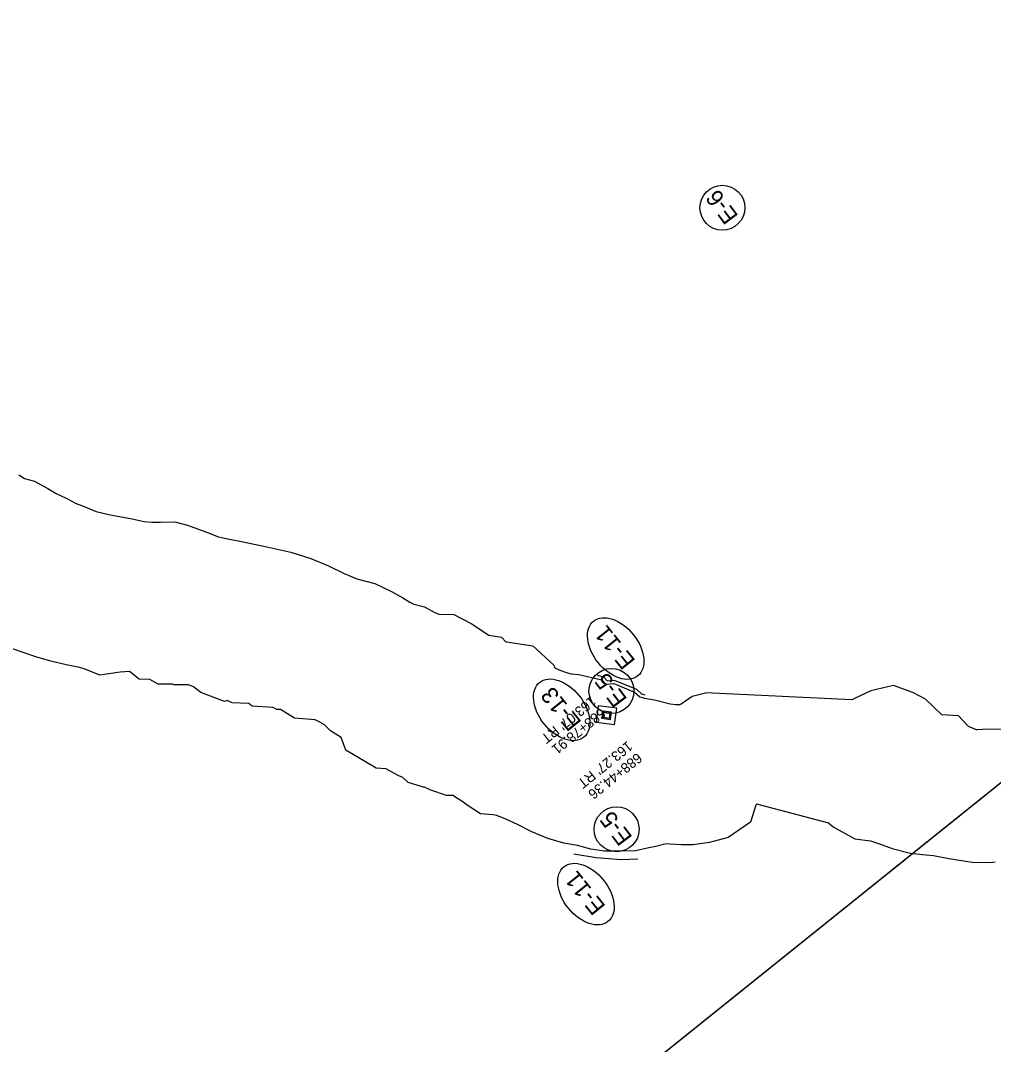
# Model space of a CAD drawing. Extents: x 641687 to 655797, y 406445 to 431088.
# Drawn here: x 651614 to 652196, y 415670 to 416282 of the extents above; entities that cross this region are included whole.
import ezdxf

# ---------------------------------------------------------------- set-up
doc = ezdxf.new("R2010")
doc.units = 0
for name, color, linetype in [('2', 7, 'Continuous'), ('R_Erosion', 7, 'Continuous'), ('R_Erosion_Buffer', 7, 'Continuous'), ('R_Erosion_Silt Fence', 7, 'Continuous'), ('R_No Plot', 7, 'Continuous')]:
    doc.layers.add(name, color=color, linetype=linetype)

msp = doc.modelspace()

# ---------------------------------------------------------------- linework, layer by layer
at = {"layer": '2'}
msp.add_lwpolyline([(651966.84, 415867.96), (651962.87, 415868.46), (651962.49, 415865.48), (651966.46, 415864.98)], close=True, dxfattribs=at)
at = {"layer": 'R_Erosion'}
for points in [[(651958.33, 415862.58), (651969.43, 415861.18), (651970.66, 415870.93), (651959.56, 415872.33)], [(651961.75, 415864.91), (651967.04, 415864.24), (651967.58, 415868.54), (651962.29, 415869.21)]]:
    msp.add_lwpolyline(points, close=True, dxfattribs=at)
for centre in [(652033.84, 416170.11), (651967.54, 415881.2), (651970.62, 415798.56)]:
    msp.add_circle(centre, 13.44, dxfattribs=at)
for centre in [(651970.07, 415906.6), (651937.8, 415869.96), (651952.29, 415759.77)]:
    msp.add_ellipse(centre, major_axis=(-13.17, 16.41), ratio=0.638788, dxfattribs=at)
at = {"layer": 'R_Erosion_Buffer'}
for points in [[(651613.34, 416010.39), (651616.81, 416008.23), (651622.73, 416006.75), (651630.66, 416002.24), (651635.68, 415999.22), (651641.68, 415996.41), (651647.68, 415993.25), (651652.55, 415991.52), (651659.6, 415988.57), (651667.91, 415986.59), (651680.14, 415984.28), (651688.33, 415982.5), (651692.94, 415982.19), (651698.1, 415982.19), (651706.63, 415982.38), (651714.19, 415980.41), (651726.07, 415975.87), (651732.76, 415973.4), (651737.24, 415972.47), (651747.46, 415970.39), (651761.51, 415967.35), (651776.01, 415964.13), (651787.93, 415960.46), (651798.52, 415955.94), (651807.85, 415951.37), (651815.38, 415948.32), (651826.1, 415945.41), (651836.04, 415940.69), (651842.87, 415936.96), (651847.05, 415934.28), (651849.53, 415933.11), (651855.8, 415931.48), (651861.67, 415928.37), (651864.4, 415927.2), (651864.66, 415927.16), (651873.37, 415926.9), (651883.63, 415921.47), (651894.28, 415914.64), (651901.84, 415913.43), (651904.5, 415910.58), (651904.84, 415910.64), (651920.51, 415908.19), (651933.13, 415896.62), (651933.78, 415895.05), (651936.66, 415893.71), (651941.22, 415892.16), (651943.51, 415891.38), (651948.08, 415891.09), (651961.8, 415887.86), (651964.2, 415885.25), (651968.86, 415885.7), (651981.35, 415880.5), (651984.59, 415877.68), (651987.34, 415876.98), (651993.29, 415875.86), (652002.65, 415873.46), (652006.05, 415873.19), (652008.48, 415873.1), (652009.13, 415873.47), (652015.81, 415878.07), (652023.69, 415880.17)], [(651613.34, 416010.39), (651616.81, 416008.23), (651622.73, 416006.75), (651630.66, 416002.24), (651635.68, 415999.22), (651641.68, 415996.41), (651647.68, 415993.25), (651652.55, 415991.52), (651659.6, 415988.57), (651667.91, 415986.59), (651680.14, 415984.28), (651688.33, 415982.5), (651692.94, 415982.19), (651698.1, 415982.19), (651706.63, 415982.38), (651714.19, 415980.41), (651726.07, 415975.87), (651732.76, 415973.4), (651737.24, 415972.47), (651747.46, 415970.39), (651761.51, 415967.35), (651776.01, 415964.13), (651787.93, 415960.46), (651798.52, 415955.94), (651807.85, 415951.37), (651815.38, 415948.32), (651826.1, 415945.41), (651836.04, 415940.69), (651842.87, 415936.96), (651847.05, 415934.28), (651849.53, 415933.11), (651855.8, 415931.48), (651861.67, 415928.37), (651864.4, 415927.2), (651864.66, 415927.16), (651873.37, 415926.9), (651883.63, 415921.47), (651894.28, 415914.64), (651901.84, 415913.43), (651904.5, 415910.58), (651904.84, 415910.64), (651920.51, 415908.19), (651933.13, 415896.62), (651933.78, 415895.05), (651936.66, 415893.71), (651941.22, 415892.16), (651943.51, 415891.38), (651948.08, 415891.09), (651961.8, 415887.86), (651964.2, 415885.25), (651968.86, 415885.7), (651981.35, 415880.5), (651984.59, 415877.68), (651987.34, 415876.98), (651993.29, 415875.86), (652002.65, 415873.46), (652006.05, 415873.19), (652008.48, 415873.1), (652009.13, 415873.47), (652015.81, 415878.07), (652023.69, 415880.17)], [(651613.34, 416010.39), (651616.81, 416008.23), (651622.73, 416006.75), (651630.66, 416002.24), (651635.68, 415999.22), (651641.68, 415996.41), (651647.68, 415993.25), (651652.55, 415991.52), (651659.6, 415988.57), (651667.91, 415986.59), (651680.14, 415984.28), (651688.33, 415982.5), (651692.94, 415982.19), (651698.1, 415982.19), (651706.63, 415982.38), (651714.19, 415980.41), (651726.07, 415975.87), (651732.76, 415973.4), (651737.24, 415972.47), (651747.46, 415970.39), (651761.51, 415967.35), (651776.01, 415964.13), (651787.93, 415960.46), (651798.52, 415955.94), (651807.85, 415951.37), (651815.38, 415948.32), (651826.1, 415945.41), (651836.04, 415940.69), (651842.87, 415936.96), (651847.05, 415934.28), (651849.53, 415933.11), (651855.8, 415931.48), (651861.67, 415928.37), (651864.4, 415927.2), (651864.66, 415927.16), (651873.37, 415926.9), (651883.63, 415921.47), (651894.28, 415914.64), (651901.84, 415913.43), (651904.5, 415910.58), (651904.84, 415910.64), (651920.51, 415908.19), (651933.13, 415896.62), (651933.78, 415895.05), (651936.66, 415893.71), (651941.22, 415892.16), (651943.51, 415891.38), (651948.08, 415891.09), (651961.8, 415887.86), (651964.2, 415885.25), (651968.86, 415885.7), (651981.35, 415880.5), (651984.59, 415877.68), (651987.34, 415876.98), (651993.29, 415875.86), (652002.65, 415873.46), (652006.05, 415873.19), (652008.48, 415873.1), (652009.13, 415873.47), (652015.81, 415878.07), (652023.69, 415880.17)], [(652054.15, 415813.85), (652053.74, 415812.95), (652050.72, 415802.88), (652037.23, 415793.7), (652026.17, 415790.72), (652016.28, 415789.28), (652009.28, 415789.28), (652002.35, 415789.56), (652000.17, 415789.84), (651994.09, 415788.32), (651989.89, 415787.53), (651981.96, 415785.71), (651973.45, 415785.52), (651963.45, 415785.52), (651955.26, 415786.72), (651947.23, 415788.8), (651939.11, 415790.24), (651929.44, 415793.12), (651919.95, 415797.08), (651911.49, 415801.38), (651904.35, 415804.68), (651899.07, 415806.73), (651896.79, 415807.26), (651889.29, 415807.86), (651881.29, 415813.04), (651878.16, 415815.33), (651874.6, 415817.6), (651872.91, 415818.71), (651868.91, 415818.66), (651859.53, 415821.89), (651855.81, 415823.65), (651855.27, 415823.78), (651846.13, 415826.45), (651842.92, 415829.45), (651840.42, 415830.59), (651833.05, 415834.57), (651833, 415834.6), (651826.97, 415835.1), (651808.81, 415845.83), (651806.09, 415853.45), (651799.75, 415857.48), (651796.02, 415860.96), (651793.29, 415862.65), (651790.84, 415863.87), (651790.3, 415864.05), (651788.02, 415864.1), (651778.08, 415864.88), (651769.75, 415870.09), (651767.6, 415870.22), (651765.38, 415871.27), (651752.83, 415872.1), (651750.82, 415873.83), (651740.87, 415874.12), (651737.85, 415875.49), (651736.28, 415874.88), (651722.23, 415880.29), (651717.99, 415883.56), (651717.38, 415883.91), (651714.54, 415884.84), (651706.12, 415884.84), (651705.26, 415885.34), (651696.61, 415885.34), (651691.71, 415888.14), (651685.34, 415888.38), (651679.48, 415892.87), (651673.93, 415892.4), (651661.79, 415890.7), (651652.5, 415894.47), (651649.58, 415895.23), (651641.78, 415896.79), (651632.52, 415899.04), (651623.57, 415901.7), (651609.68, 415906.37)], [(652054.15, 415813.85), (652053.74, 415812.95), (652050.72, 415802.88), (652037.23, 415793.7), (652026.17, 415790.72), (652016.28, 415789.28), (652009.28, 415789.28), (652002.35, 415789.56), (652000.17, 415789.84), (651994.09, 415788.32), (651989.89, 415787.53), (651981.96, 415785.71), (651973.45, 415785.52), (651963.45, 415785.52), (651955.26, 415786.72), (651947.23, 415788.8), (651939.11, 415790.24), (651929.44, 415793.12), (651919.95, 415797.08), (651911.49, 415801.38), (651904.35, 415804.68), (651899.07, 415806.73), (651896.79, 415807.26), (651889.29, 415807.86), (651881.29, 415813.04), (651878.16, 415815.33), (651874.6, 415817.6), (651872.91, 415818.71), (651868.91, 415818.66), (651859.53, 415821.89), (651855.81, 415823.65), (651855.27, 415823.78), (651846.13, 415826.45), (651842.92, 415829.45), (651840.42, 415830.59), (651833.05, 415834.57), (651833, 415834.6), (651826.97, 415835.1), (651808.81, 415845.83), (651806.09, 415853.45), (651799.75, 415857.48), (651796.02, 415860.96), (651793.29, 415862.65), (651790.84, 415863.87), (651790.3, 415864.05), (651788.02, 415864.1), (651778.08, 415864.88), (651769.75, 415870.09), (651767.6, 415870.22), (651765.38, 415871.27), (651752.83, 415872.1), (651750.82, 415873.83), (651740.87, 415874.12), (651737.85, 415875.49), (651736.28, 415874.88), (651722.23, 415880.29), (651717.99, 415883.56), (651717.38, 415883.91), (651714.54, 415884.84), (651706.12, 415884.84), (651705.26, 415885.34), (651696.61, 415885.34), (651691.71, 415888.14), (651685.34, 415888.38), (651679.48, 415892.87), (651673.93, 415892.4), (651661.79, 415890.7), (651652.5, 415894.47), (651649.58, 415895.23), (651641.78, 415896.79), (651632.52, 415899.04), (651623.57, 415901.7), (651609.68, 415906.37)], [(652054.15, 415813.85), (652053.74, 415812.95), (652050.72, 415802.88), (652037.23, 415793.7), (652026.17, 415790.72), (652016.28, 415789.28), (652009.28, 415789.28), (652002.35, 415789.56), (652000.17, 415789.84), (651994.09, 415788.32), (651989.89, 415787.53), (651981.96, 415785.71), (651973.45, 415785.52), (651963.45, 415785.52), (651955.26, 415786.72), (651947.23, 415788.8), (651939.11, 415790.24), (651929.44, 415793.12), (651919.95, 415797.08), (651911.49, 415801.38), (651904.35, 415804.68), (651899.07, 415806.73), (651896.79, 415807.26), (651889.29, 415807.86), (651881.29, 415813.04), (651878.16, 415815.33), (651874.6, 415817.6), (651872.91, 415818.71), (651868.91, 415818.66), (651859.53, 415821.89), (651855.81, 415823.65), (651855.27, 415823.78), (651846.13, 415826.45), (651842.92, 415829.45), (651840.42, 415830.59), (651833.05, 415834.57), (651833, 415834.6), (651826.97, 415835.1), (651808.81, 415845.83), (651806.09, 415853.45), (651799.75, 415857.48), (651796.02, 415860.96), (651793.29, 415862.65), (651790.84, 415863.87), (651790.3, 415864.05), (651788.02, 415864.1), (651778.08, 415864.88), (651769.75, 415870.09), (651767.6, 415870.22), (651765.38, 415871.27), (651752.83, 415872.1), (651750.82, 415873.83), (651740.87, 415874.12), (651737.85, 415875.49), (651736.28, 415874.88), (651722.23, 415880.29), (651717.99, 415883.56), (651717.38, 415883.91), (651714.54, 415884.84), (651706.12, 415884.84), (651705.26, 415885.34), (651696.61, 415885.34), (651691.71, 415888.14), (651685.34, 415888.38), (651679.48, 415892.87), (651673.93, 415892.4), (651661.79, 415890.7), (651652.5, 415894.47), (651649.58, 415895.23), (651641.78, 415896.79), (651632.52, 415899.04), (651623.57, 415901.7), (651609.68, 415906.37)], [(652202.83, 415858.26), (652192.41, 415858.41), (652186.14, 415858.05), (652185.58, 415858.03), (652180.91, 415860.07), (652180.78, 415860.14), (652174.88, 415866.43), (652165.03, 415866.88), (652155.13, 415876.33), (652147.72, 415880.33), (652136.08, 415884.49), (652122.57, 415881.4), (652112.73, 415876.74), (652111.33, 415875.84), (652023.69, 415880.17)], [(652202.83, 415858.26), (652192.41, 415858.41), (652186.14, 415858.05), (652185.58, 415858.03), (652180.91, 415860.07), (652180.78, 415860.14), (652174.88, 415866.43), (652165.03, 415866.88), (652155.13, 415876.33), (652147.72, 415880.33), (652136.08, 415884.49), (652122.57, 415881.4), (652112.73, 415876.74), (652111.33, 415875.84), (652023.69, 415880.17)], [(652202.83, 415858.26), (652192.41, 415858.41), (652186.14, 415858.05), (652185.58, 415858.03), (652180.91, 415860.07), (652180.78, 415860.14), (652174.88, 415866.43), (652165.03, 415866.88), (652155.13, 415876.33), (652147.72, 415880.33), (652136.08, 415884.49), (652122.57, 415881.4), (652112.73, 415876.74), (652111.33, 415875.84), (652023.69, 415880.17)], [(652054.15, 415813.85), (652097.14, 415802.49), (652099.99, 415799.94), (652113.03, 415792.88), (652122.34, 415791.57), (652127.13, 415790.1), (652135.29, 415787.14), (652146.16, 415784.26), (652153.4, 415783.49), (652160.01, 415782.95), (652169.13, 415781.01), (652183.07, 415778.82), (652194.13, 415778.64), (652196.82, 415779.11)], [(652054.15, 415813.85), (652097.14, 415802.49), (652099.99, 415799.94), (652113.03, 415792.88), (652122.34, 415791.57), (652127.13, 415790.1), (652135.29, 415787.14), (652146.16, 415784.26), (652153.4, 415783.49), (652160.01, 415782.95), (652169.13, 415781.01), (652183.07, 415778.82), (652194.13, 415778.64), (652196.82, 415779.11)], [(652054.15, 415813.85), (652097.14, 415802.49), (652099.99, 415799.94), (652113.03, 415792.88), (652122.34, 415791.57), (652127.13, 415790.1), (652135.29, 415787.14), (652146.16, 415784.26), (652153.4, 415783.49), (652160.01, 415782.95), (652169.13, 415781.01), (652183.07, 415778.82), (652194.13, 415778.64), (652196.82, 415779.11)]]:
    msp.add_lwpolyline(points, dxfattribs=at)
at = {"layer": 'R_Erosion_Silt Fence'}
for p, q in [((651958.92, 415890.59), (651962.86, 415889.66)), ((651962.86, 415889.66), (651965, 415887.34)), ((651965, 415887.34), (651969.17, 415887.74)), ((651969.17, 415887.74), (651982.42, 415882.22)), ((651982.42, 415882.22), (651985.54, 415879.5)), ((651985.54, 415879.5), (651987.44, 415879.02)), ((651958.49, 415781.51), (651945.14, 415783.66)), ((651973.44, 415780.33), (651958.49, 415781.51)), ((651983.24, 415780.77), (651973.44, 415780.33))]:
    msp.add_line(p, q, dxfattribs=at)
at = {"layer": 'R_No Plot'}
for points in [[(651236.95, 418130.67), (649657.6, 416862.95), (649657.6, 416862.95), (651159.93, 414991.32), (652739.27, 416259.04)], [(652739.85, 416259.5), (651159.36, 414990.86), (651159.36, 414990.86), (652478.68, 413212.47), (654004.2, 414041.19), (654250.16, 414223.66)]]:
    msp.add_lwpolyline(points, close=True, dxfattribs=at)

# ---------------------------------------------------------------- texts
at = {"layer": 'R_Erosion'}
for s, rotation, p in [('E-6', 126.92325, (652043.71, 416165.17)), ('E-11', 128.75345, (651982.23, 415899.3)), ('E-5', 126.92325, (651977.34, 415876.36)), ('E-13', 128.75345, (651950.07, 415862.53)), ('E-5', 126.92325, (651980.41, 415793.72)), ('E-11', 128.75345, (651964.45, 415752.48))]:
    msp.add_text(s, height=10, rotation=rotation, dxfattribs=at).set_placement(p)
at = {"layer": 'R_No Plot'}
for s, p in [("163.07' RT  ", (651955.39, 415878.48)), ('688+78.91 ', (651961.02, 415871.46)), ("163.27' RT  ", (651977.17, 415851.65)), ('688+44.36 ', (651982.81, 415844.63))]:
    msp.add_text(s, height=6, rotation=218.75345, dxfattribs=at).set_placement(p)

doc.saveas('drawing.dxf')
